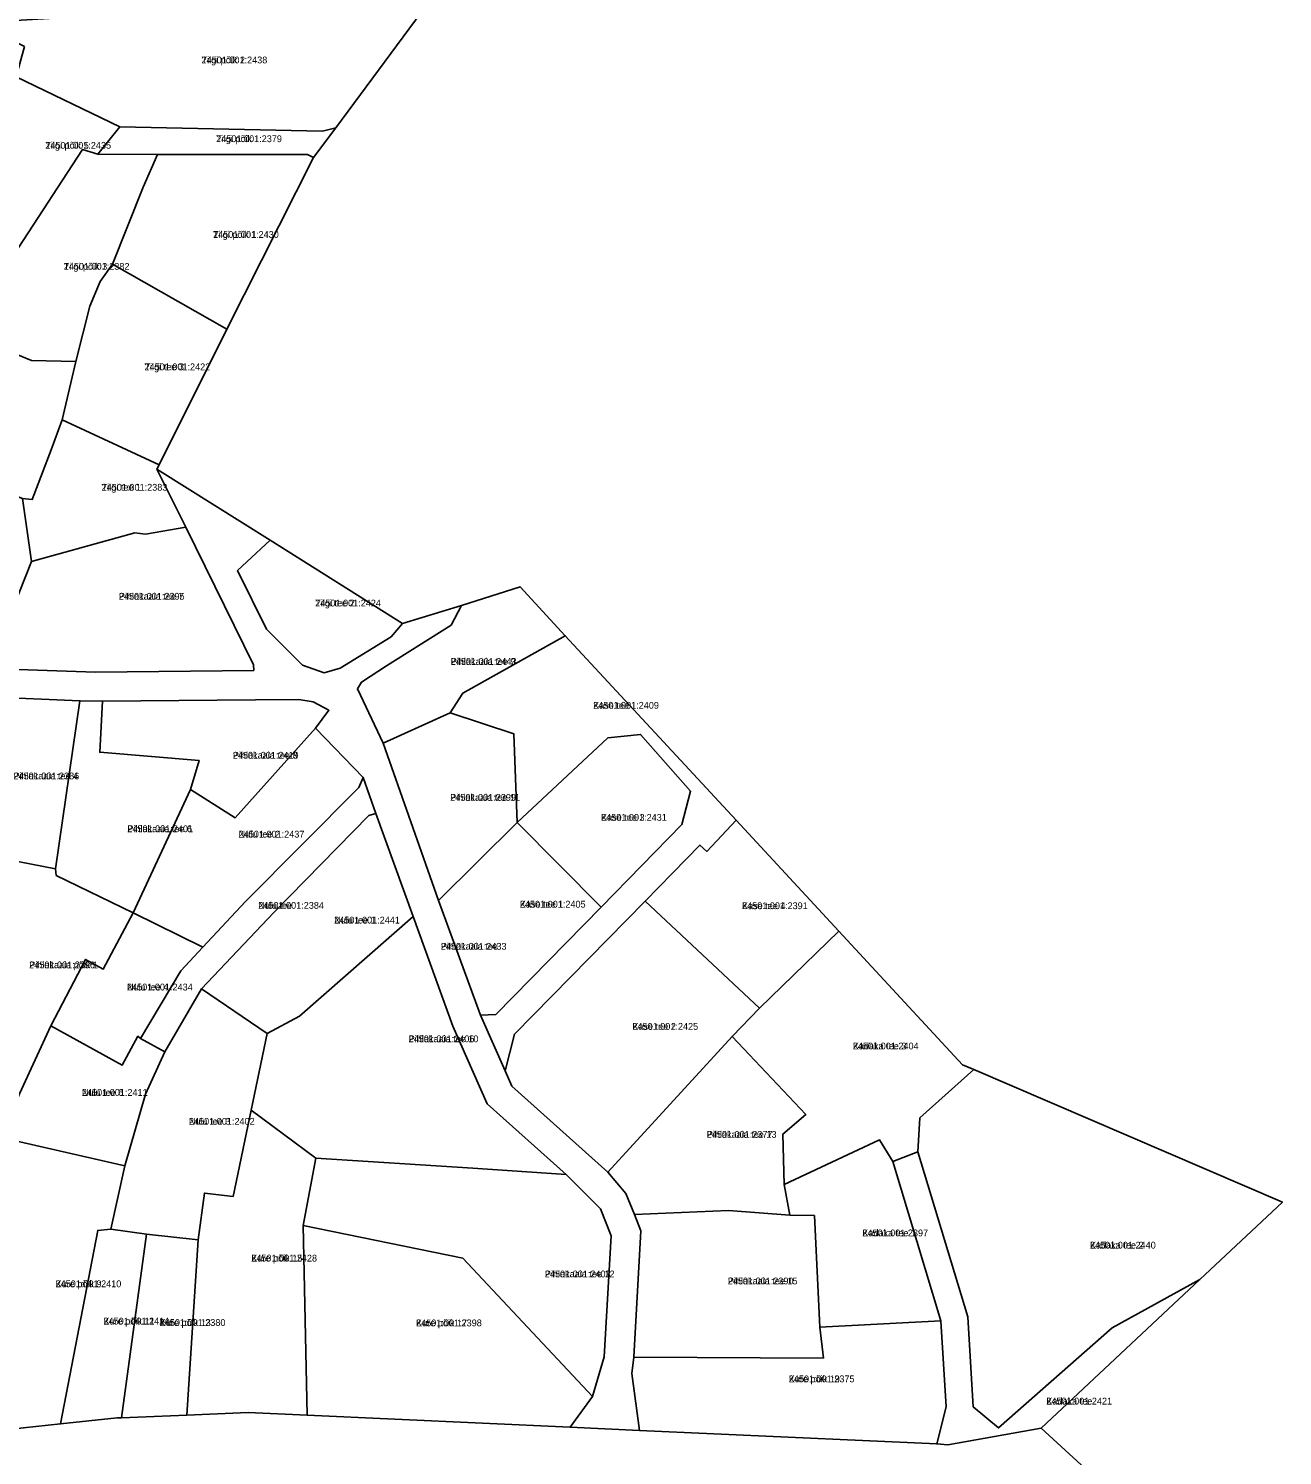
# Model space of a CAD drawing. Extents: x 551291 to 575799, y 6581704 to 6610137.
# Drawn here: x 559526.5 to 559803.1, y 6593898.5 to 6594213.3 of the extents above; entities that cross this region are included whole.
import ezdxf

# ---------------------------------------------------------------- set-up
doc = ezdxf.new("R2010")
doc.units = 0
for name, color, linetype in [('L_AADRESS', 7, 'Continuous'), ('PIIR', 7, 'Continuous'), ('TUNNUS', 7, 'Continuous')]:
    doc.layers.add(name, color=color, linetype=linetype)

msp = doc.modelspace()

# ---------------------------------------------------------------- linework, layer by layer
at = {"layer": 'PIIR'}
for points in [[(559525.57, 6594209.38), (559514.78, 6594214.62), (559615.8, 6594220.58), (559594.25, 6594191.44), (559591.29, 6594190.7), (559546.62, 6594191.67), (559523.72, 6594202.7)], [(559513.75, 6594170.78), (559523.72, 6594202.7), (559546.62, 6594191.67), (559541.73, 6594185.64), (559538.41, 6594186.65), (559524.21, 6594164.88)], [(559541.73, 6594185.64), (559546.62, 6594191.67), (559591.29, 6594190.7), (559594.25, 6594191.44), (559589.35, 6594184.84), (559588.03, 6594185.54), (559554.94, 6594185.57)], [(559524.21, 6594164.88), (559538.41, 6594186.65), (559541.73, 6594185.64), (559554.94, 6594185.57), (559551.76, 6594178.32), (559545, 6594161.31), (559542.31, 6594157.52), (559540, 6594152.04), (559536.9, 6594139.9), (559527.11, 6594140.11), (559513.56, 6594145.66)], [(559551.76, 6594178.32), (559554.94, 6594185.57), (559588.03, 6594185.54), (559589.35, 6594184.84), (559570.24, 6594146.99), (559545, 6594161.31)], [(559453.77, 6594133.23), (559468.99, 6594164.84), (559505.93, 6594148.22), (559513.56, 6594145.66), (559527.11, 6594140.11), (559536.9, 6594139.9), (559533.88, 6594127.02), (559531.45, 6594120.4), (559527.29, 6594109.45), (559525.12, 6594109.62), (559514.29, 6594113.8), (559510.75, 6594112.49), (559503.57, 6594115.15), (559482.5, 6594122.71)], [(559542.31, 6594157.52), (559545, 6594161.31), (559570.24, 6594146.99), (559555.26, 6594117.08), (559533.88, 6594127.02), (559536.9, 6594139.9), (559540, 6594152.04)], [(559531.45, 6594120.4), (559533.88, 6594127.02), (559555.26, 6594117.08), (559554.81, 6594116.14), (559561.17, 6594103.3), (559552.29, 6594101.8), (559549.96, 6594102.04), (559527.12, 6594095.71), (559525.12, 6594109.62), (559527.29, 6594109.45)], [(559494.8, 6594074.46), (559503.57, 6594115.15), (559510.75, 6594112.49), (559514.29, 6594113.8), (559525.12, 6594109.62), (559527.12, 6594095.71), (559517.71, 6594072.17)], [(559517.71, 6594072.17), (559527.12, 6594095.71), (559549.96, 6594102.04), (559552.29, 6594101.8), (559561.17, 6594103.3), (559576.1, 6594072.98), (559576.14, 6594071.72), (559541.24, 6594071.33)], [(559572.58, 6594093.75), (559579.75, 6594100.48), (559608.94, 6594082.05), (559606.47, 6594079.14), (559595.25, 6594072.18), (559591.65, 6594071.18), (559586.93, 6594072.88), (559578.94, 6594080.82)], [(559619.67, 6594081.69), (559621.96, 6594086.06), (559634.92, 6594090.18), (559644.86, 6594079.38), (559622.28, 6594066.7), (559619.48, 6594062.39), (559604.72, 6594055.7), (559599.02, 6594067.62), (559599.9, 6594069.16), (559605.44, 6594072.71)], [(559619.48, 6594062.39), (559622.28, 6594066.7), (559644.86, 6594079.38), (559682.56, 6594038.65), (559676.06, 6594031.77), (559674.56, 6594033.19), (559662.52, 6594020.78), (559633.65, 6593991.47), (559631.63, 6593983.36), (559626.16, 6593995.64), (559629.54, 6593995.82), (559652.79, 6594019.5), (559670.61, 6594037.74), (559672.52, 6594045.07), (559661.46, 6594057.61), (559654.28, 6594056.86), (559634.26, 6594038.15), (559633.5, 6594057.73)], [(559508.5, 6594032.57), (559517.34, 6594065.86), (559537.81, 6594065.01), (559532.45, 6594027.95)], [(559542.19, 6594053.68), (559542.79, 6594064.94), (559576.53, 6594065.24), (559586.09, 6594065.29), (559589.23, 6594064.77), (559592.73, 6594062.92), (559589.79, 6594059), (559572.05, 6594039.22), (559562.23, 6594045.42), (559564.09, 6594051.86)], [(559532.45, 6594027.95), (559537.81, 6594065.01), (559542.79, 6594064.94), (559542.19, 6594053.68), (559564.09, 6594051.86), (559562.23, 6594045.42), (559549.59, 6594018.25), (559532.61, 6594026.5)], [(559616.91, 6594020.96), (559604.72, 6594055.7), (559619.48, 6594062.39), (559633.5, 6594057.73), (559634.26, 6594038.15)], [(559549.59, 6594018.25), (559562.23, 6594045.42), (559572.05, 6594039.22), (559589.79, 6594059), (559600.31, 6594048.1), (559599.31, 6594045.91), (559574.37, 6594020.76), (559564.96, 6594010.67)], [(559652.79, 6594019.5), (559634.26, 6594038.15), (559654.28, 6594056.86), (559661.46, 6594057.61), (559672.52, 6594045.07), (559670.61, 6594037.74)], [(559599.31, 6594045.91), (559600.31, 6594048.1), (559603.07, 6594040.16), (559601.56, 6594039.68), (559580.55, 6594018.33), (559564.66, 6594001.47), (559556.52, 6593987.57), (559551.21, 6593990.48), (559560.04, 6594005.47), (559564.96, 6594010.67), (559574.37, 6594020.76)], [(559579.11, 6593991.59), (559564.66, 6594001.47), (559580.55, 6594018.33), (559601.56, 6594039.68), (559603.07, 6594040.16), (559611.29, 6594017.41), (559586.27, 6593995.43)], [(559626.16, 6593995.64), (559616.91, 6594020.96), (559634.26, 6594038.15), (559652.79, 6594019.5), (559629.54, 6593995.82)], [(559687.71, 6593997.22), (559662.52, 6594020.78), (559674.56, 6594033.19), (559676.06, 6594031.77), (559682.56, 6594038.65), (559705.17, 6594014.19)], [(559503.8, 6594013.56), (559508.5, 6594032.57), (559532.45, 6594027.95), (559532.61, 6594026.5), (559549.59, 6594018.25), (559542.97, 6594005.83), (559539.06, 6594007.96), (559531.43, 6593993.29), (559524.48, 6593978.3), (559510.5, 6593984.68), (559518.14, 6594002.71), (559503.67, 6594008.61)], [(559542.97, 6594005.83), (559549.59, 6594018.25), (559564.96, 6594010.67), (559560.04, 6594005.47), (559551.21, 6593990.48), (559550.59, 6593991.01), (559547.14, 6593984.63), (559531.43, 6593993.29), (559539.06, 6594007.96)], [(559633.09, 6593979.99), (559631.63, 6593983.36), (559633.65, 6593991.47), (559662.52, 6594020.78), (559687.71, 6593997.22), (559681.64, 6593990.95), (559654.22, 6593961.03)], [(559575.6, 6593974.67), (559579.11, 6593991.59), (559586.27, 6593995.43), (559611.29, 6594017.41), (559620.1, 6593993.22), (559627.65, 6593976.07), (559645.03, 6593960.5), (559624.46, 6593961.93), (559589.86, 6593964.12)], [(559722.65, 6593965.5), (559717.14, 6593963.38), (559714.14, 6593968.16), (559693.12, 6593958.28), (559692.86, 6593969.41), (559697.92, 6593973.74), (559681.64, 6593990.95), (559687.71, 6593997.22), (559705.17, 6594014.19), (559732.47, 6593984.71), (559734.96, 6593983.71), (559723.05, 6593972.98)], [(559556.52, 6593987.57), (559564.66, 6594001.47), (559579.11, 6593991.59), (559575.6, 6593974.67), (559571.61, 6593955.65), (559565.28, 6593956.42), (559563.87, 6593946.06), (559552.49, 6593947.32), (559544.62, 6593948.45), (559547.7, 6593962.42), (559552.3, 6593978.21)], [(559524.48, 6593978.3), (559531.43, 6593993.29), (559547.14, 6593984.63), (559550.59, 6593991.01), (559551.21, 6593990.48), (559556.52, 6593987.57), (559552.3, 6593978.21), (559547.7, 6593962.42), (559520.38, 6593968.65), (559522.99, 6593974.73)], [(559658.2, 6593956.33), (559654.22, 6593961.03), (559681.64, 6593990.95), (559697.92, 6593973.74), (559692.86, 6593969.41), (559693.12, 6593958.28), (559694.39, 6593951.56), (559680.87, 6593952.56), (559660.11, 6593951.65)], [(559733.67, 6593929.08), (559722.65, 6593965.5), (559723.05, 6593972.98), (559734.96, 6593983.71), (559803.05, 6593954.4), (559784.8, 6593937.35), (559765.47, 6593926.68), (559740.44, 6593904.62), (559734.84, 6593909.25)], [(559561.37, 6593907.45), (559563.87, 6593946.06), (559565.28, 6593956.42), (559571.61, 6593955.65), (559575.6, 6593974.67), (559589.86, 6593964.12), (559587.09, 6593949.25), (559587.97, 6593907.39), (559574.95, 6593908)], [(559517.17, 6593903.73), (559520.38, 6593968.65), (559547.7, 6593962.42), (559544.62, 6593948.45), (559541.76, 6593948.19), (559533.53, 6593905.49)], [(559694.39, 6593951.56), (559693.12, 6593958.28), (559714.14, 6593968.16), (559717.14, 6593963.38), (559727.67, 6593928.26), (559701.02, 6593926.84), (559699.8, 6593951.45)], [(559728.84, 6593909.27), (559727.67, 6593928.26), (559717.14, 6593963.38), (559722.65, 6593965.5), (559733.67, 6593929.08), (559734.84, 6593909.25), (559740.44, 6593904.62), (559765.47, 6593926.68), (559784.8, 6593937.35), (559749.81, 6593904.53), (559729.26, 6593900.9), (559726.81, 6593901.07)], [(559587.09, 6593949.25), (559589.86, 6593964.12), (559624.46, 6593961.93), (559645.03, 6593960.5), (559652.61, 6593952.94), (559655.02, 6593946.99), (559653.45, 6593920.28), (559650.86, 6593911.52), (559622.27, 6593942.05)], [(559661.53, 6593948.08), (559660.11, 6593951.65), (559680.87, 6593952.56), (559694.39, 6593951.56), (559699.8, 6593951.45), (559701.02, 6593926.84), (559701.82, 6593919.99), (559659.97, 6593920.24)], [(559587.97, 6593907.39), (559587.09, 6593949.25), (559622.27, 6593942.05), (559650.86, 6593911.52), (559645.96, 6593904.78)], [(559533.53, 6593905.49), (559541.76, 6593948.19), (559544.62, 6593948.45), (559552.49, 6593947.32), (559546.95, 6593906.86), (559546.01, 6593906.83)], [(559546.95, 6593906.86), (559552.49, 6593947.32), (559563.87, 6593946.06), (559561.37, 6593907.45)], [(559659.55, 6593916.64), (559659.97, 6593920.24), (559701.82, 6593919.99), (559701.02, 6593926.84), (559727.67, 6593928.26), (559728.84, 6593909.27), (559726.81, 6593901.07), (559661.24, 6593904.06)]]:
    msp.add_lwpolyline(points, close=True, dxfattribs=at)
for points in [[(559771.03, 6593885.13), (559749.81, 6593904.53), (559784.8, 6593937.35), (559803.05, 6593954.4), (559734.96, 6593983.71), (559732.47, 6593984.71), (559705.17, 6594014.19), (559682.56, 6594038.65), (559644.86, 6594079.38), (559634.92, 6594090.18), (559621.96, 6594086.06), (559608.94, 6594082.05), (559579.75, 6594100.48), (559554.81, 6594116.14), (559555.26, 6594117.08), (559570.24, 6594146.99), (559589.35, 6594184.84), (559594.25, 6594191.44), (559615.8, 6594220.58)], [(559517.71, 6594072.17), (559541.24, 6594071.33), (559576.14, 6594071.72), (559576.1, 6594072.98), (559561.17, 6594103.3), (559554.81, 6594116.14), (559579.75, 6594100.48), (559572.58, 6594093.75), (559578.94, 6594080.82), (559586.93, 6594072.88), (559591.65, 6594071.18), (559595.25, 6594072.18), (559606.47, 6594079.14), (559608.94, 6594082.05), (559621.96, 6594086.06), (559619.67, 6594081.69), (559605.44, 6594072.71), (559599.9, 6594069.16), (559599.02, 6594067.62), (559604.72, 6594055.7), (559616.91, 6594020.96), (559626.16, 6593995.64), (559631.63, 6593983.36), (559633.09, 6593979.99), (559654.22, 6593961.03), (559658.2, 6593956.33), (559660.11, 6593951.65), (559661.53, 6593948.08), (559659.97, 6593920.24), (559659.55, 6593916.64), (559661.24, 6593904.06), (559645.96, 6593904.78), (559650.86, 6593911.52), (559653.45, 6593920.28), (559655.02, 6593946.99), (559652.61, 6593952.94), (559645.03, 6593960.5), (559627.65, 6593976.07), (559620.1, 6593993.22), (559611.29, 6594017.41), (559603.07, 6594040.16), (559600.31, 6594048.1), (559589.79, 6594059), (559592.73, 6594062.92), (559589.23, 6594064.77), (559586.09, 6594065.29), (559576.53, 6594065.24), (559542.79, 6594064.94), (559537.81, 6594065.01), (559517.34, 6594065.86)], [(559517.17, 6593903.73), (559533.53, 6593905.49), (559546.01, 6593906.83), (559546.95, 6593906.86), (559561.37, 6593907.45), (559574.95, 6593908), (559587.97, 6593907.39), (559645.96, 6593904.78), (559661.24, 6593904.06), (559726.81, 6593901.07), (559729.26, 6593900.9), (559749.81, 6593904.53), (559771.03, 6593885.13), (559771.89, 6593880.29), (559622.34, 6593896.15), (559620.01, 6593893.86), (559575.36, 6593895.99), (559547.24, 6593894.87), (559454.05, 6593884.92)]]:
    msp.add_lwpolyline(points, dxfattribs=at)

# ---------------------------------------------------------------- texts
at = {"layer": 'L_AADRESS'}
for s, p in [('Tiigi põik 2', (559564.64, 6594205.64)), ('Tiigi põik 5', (559530.18, 6594186.81)), ('Tiigi põik', (559567.87, 6594188.26)), ('Tiigi põik 1', (559567.18, 6594167.14)), ('Tiigi põik 3', (559534.25, 6594160.11)), ('Tiigi tee 3', (559552.06, 6594137.94)), ('Tiigi tee 1', (559542.6, 6594111.37)), ('Pihlakaaia tee 7', (559546.4, 6594087.32)), ('Tiigi tee 2', (559589.71, 6594085.83)), ('Pihlakaaia tee 9', (559619.6, 6594072.94)), ('Kase tee', (559651.02, 6594063.27)), ('Pihlakaaia tee 8', (559571.54, 6594052.25)), ('Pihlakaaia tee 4', (559523.16, 6594047.68)), ('Pihlakaaia tee 11', (559619.49, 6594042.95)), ('Kase tee 3', (559652.76, 6594038.55)), ('Pihlakaaia tee 6', (559548.27, 6594036.03)), ('Nulu tee 2', (559572.82, 6594034.84)), ('Nulu tee', (559577.14, 6594019.13)), ('Kase tee 1', (559634.85, 6594019.39)), ('Kase tee 4', (559683.85, 6594019.05)), ('Nulu tee 1', (559593.89, 6594015.88)), ('Pihlakaaia tee', (559617.41, 6594010.1)), ('Pihlakaaia põik 1', (559526.63, 6594006)), ('Nulu tee 4', (559548.2, 6594001.11)), ('Kase tee 2', (559659.67, 6593992.43)), ('Pihlakaaia tee 10', (559610.32, 6593989.69)), ('Kadaka tee 3', (559708.3, 6593988.11)), ('Nulu tee 6', (559538.25, 6593977.86)), ('Nulu tee 3', (559561.86, 6593971.49)), ('Pihlakaaia tee 13', (559676.07, 6593968.61)), ('Kadaka tee 1', (559710.39, 6593946.87)), ('Kadaka tee 2', (559760.6, 6593944.17)), ('Kure põik 15', (559575.61, 6593941.31)), ('Pihlakaaia tee 12', (559640.36, 6593937.82)), ('Kure põik 9', (559532.44, 6593935.64)), ('Pihlakaaia tee 15', (559680.71, 6593936.27)), ('Kure põik 11', (559543.01, 6593927.41)), ('Kure põik 13', (559555.41, 6593927.1)), ('Kure põik 17', (559611.95, 6593927.02)), ('Kure põik 19', (559694.16, 6593914.67)), ('Kadaka tee', (559750.97, 6593909.76))]:
    msp.add_text(s, height=1.5, dxfattribs=at).set_placement(p)
at = {"layer": 'TUNNUS'}
for s, p in [('24501:001:2438', (559564.64, 6594205.64)), ('24501:001:2435', (559530.18, 6594186.81)), ('24501:001:2379', (559567.87, 6594188.26)), ('24501:001:2430', (559567.18, 6594167.14)), ('24501:001:2382', (559534.25, 6594160.11)), ('24501:001:2422', (559552.06, 6594137.94)), ('24501:001:2383', (559542.6, 6594111.37)), ('24501:001:2395', (559546.4, 6594087.32)), ('24501:001:2424', (559589.71, 6594085.83)), ('24501:001:2443', (559619.6, 6594072.94)), ('24501:001:2409', (559651.02, 6594063.27)), ('24501:001:2419', (559571.54, 6594052.25)), ('24501:001:2386', (559523.16, 6594047.68)), ('24501:001:2399', (559619.49, 6594042.95)), ('24501:001:2431', (559652.76, 6594038.55)), ('24501:001:2401', (559548.27, 6594036.03)), ('24501:001:2437', (559572.82, 6594034.84)), ('24501:001:2384', (559577.14, 6594019.13)), ('24501:001:2405', (559634.85, 6594019.39)), ('24501:001:2391', (559683.85, 6594019.05)), ('24501:001:2441', (559593.89, 6594015.88)), ('24501:001:2433', (559617.41, 6594010.1)), ('24501:001:2396', (559526.63, 6594006)), ('24501:001:2434', (559548.2, 6594001.11)), ('24501:001:2425', (559659.67, 6593992.43)), ('24501:001:2406', (559610.32, 6593989.69)), ('24501:001:2404', (559708.3, 6593988.11)), ('24501:001:2411', (559538.25, 6593977.86)), ('24501:001:2402', (559561.86, 6593971.49)), ('24501:001:2377', (559676.07, 6593968.61)), ('24501:001:2397', (559710.39, 6593946.87)), ('24501:001:2440', (559760.6, 6593944.17)), ('24501:001:2428', (559575.61, 6593941.31)), ('24501:001:2403', (559640.36, 6593937.82)), ('24501:001:2410', (559532.44, 6593935.64)), ('24501:001:2390', (559680.71, 6593936.27)), ('24501:001:2414', (559543.01, 6593927.41)), ('24501:001:2380', (559555.41, 6593927.1)), ('24501:001:2398', (559611.95, 6593927.02)), ('24501:001:2375', (559694.16, 6593914.67)), ('24501:001:2421', (559750.97, 6593909.76))]:
    msp.add_text(s, height=1.5, dxfattribs=at).set_placement(p)

doc.saveas('drawing.dxf')
